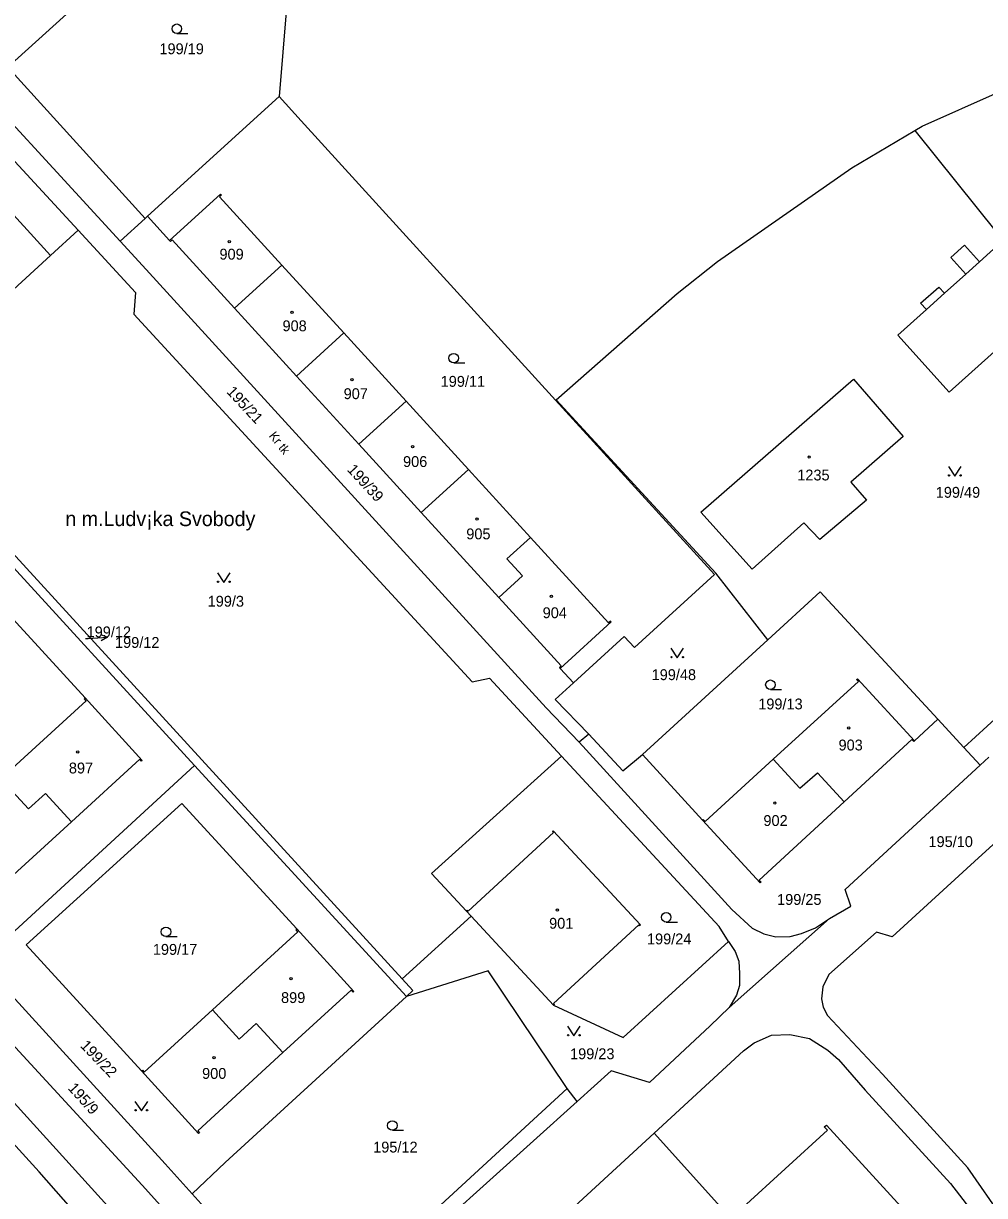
# Model space of a CAD drawing. Extents: x -735249 to -729401, y -1124843 to -1121828.
# Drawn here: x -733187.6 to -733037.1, y -1123958.8 to -1123775.2 of the extents above; entities that cross this region are included whole.
import ezdxf

# ---------------------------------------------------------------- set-up
doc = ezdxf.new("R2010")
doc.units = 0
for name, color, linetype in [('Vrstva 1', 7, 'Continuous'), ('Vrstva 15', 7, 'Continuous'), ('Vrstva 16', 7, 'Continuous'), ('Vrstva 18', 7, 'Continuous'), ('Vrstva 19', 7, 'Continuous'), ('Vrstva 25', 7, 'Continuous'), ('Vrstva 4', 7, 'Continuous')]:
    doc.layers.add(name, color=color, linetype=linetype)

msp = doc.modelspace()

# ---------------------------------------------------------------- linework, layer by layer
at = {"layer": 'Vrstva 1'}
for points in [[(-733144.76, -1123752.48), (-733147.59, -1123786.65)], [(-733178.16, -1123771.22), (-733190.05, -1123782.03)], [(-733172.46, -1123809.29), (-733201.09, -1123778.17)], [(-733179.06, -1123807.6), (-733203.9, -1123780.69)], [(-733046.92, -1123791.3), (-733023.02, -1123780.65)], [(-733168.57, -1123805.75), (-733190.05, -1123782.03)], [(-733147.59, -1123786.65), (-733168.2, -1123805.41)], [(-733147.59, -1123786.65), (-733144.14, -1123790.44)], [(-733144.14, -1123790.44), (-733104.3, -1123834.22)], [(-733057.93, -1123797.79), (-733048.04, -1123791.96)], [(-733048.04, -1123791.96), (-733046.92, -1123791.3)], [(-733048.04, -1123791.96), (-733035.11, -1123808.11)], [(-733183.39, -1123811.57), (-733200.21, -1123793.04)], [(-733078.95, -1123812.49), (-733057.93, -1123797.79)], [(-733164.73, -1123809.22), (-733156.74, -1123801.93)], [(-733156.62, -1123802.06), (-733156.93, -1123802.34)], [(-733156.93, -1123802.34), (-733147.17, -1123813.04)], [(-733156.74, -1123801.93), (-733156.62, -1123802.06)], [(-733168.2, -1123805.41), (-733168.57, -1123805.75)], [(-733168.2, -1123805.41), (-733164.73, -1123809.22)], [(-733168.57, -1123805.75), (-733172.46, -1123809.29)], [(-733183.39, -1123811.57), (-733179.06, -1123807.6)], [(-733179.06, -1123807.6), (-733170.05, -1123817.34)], [(-733164.61, -1123809.35), (-733164.73, -1123809.22)], [(-733164.31, -1123809.08), (-733164.61, -1123809.35)], [(-733154.55, -1123819.78), (-733164.31, -1123809.08)], [(-733172.46, -1123809.29), (-733168.97, -1123813.09)], [(-733042.41, -1123811.85), (-733040.27, -1123809.92)], [(-733040.27, -1123809.92), (-733037.92, -1123812.52)], [(-733037.92, -1123812.52), (-733034.6, -1123809.52)], [(-733209.79, -1123835.76), (-733183.39, -1123811.57)], [(-733085.28, -1123817.5), (-733078.95, -1123812.49)], [(-733040.06, -1123814.45), (-733042.41, -1123811.85)], [(-733105.77, -1123882.37), (-733168.97, -1123813.09)], [(-733154.55, -1123819.78), (-733147.17, -1123813.04)], [(-733147.17, -1123813.04), (-733137.46, -1123823.68)], [(-733043.41, -1123817.46), (-733040.06, -1123814.45)], [(-733047.18, -1123819), (-733044.29, -1123816.49)], [(-733044.29, -1123816.49), (-733043.41, -1123817.46)], [(-733170.05, -1123817.34), (-733170.32, -1123820.71)], [(-733104.21, -1123834.14), (-733085.28, -1123817.5)], [(-733144.85, -1123830.42), (-733154.55, -1123819.78)], [(-733050.7, -1123824.03), (-733046.25, -1123820.02)], [(-733046.25, -1123820.02), (-733047.18, -1123819)], [(-733170.32, -1123820.71), (-733117.36, -1123878.34)], [(-733144.85, -1123830.42), (-733137.46, -1123823.68)], [(-733137.46, -1123823.68), (-733127.69, -1123834.38)], [(-733042.66, -1123832.95), (-733050.7, -1123824.03)], [(-733034.6, -1123825.69), (-733042.66, -1123832.95)], [(-733135.08, -1123841.12), (-733144.85, -1123830.42)], [(-733081.56, -1123851.73), (-733057.66, -1123830.93)], [(-733057.66, -1123830.93), (-733049.86, -1123839.89)], [(-733127.69, -1123834.38), (-733135.08, -1123841.12)], [(-733117.93, -1123845.08), (-733127.69, -1123834.38)], [(-733104.3, -1123834.22), (-733104.21, -1123834.14)], [(-733079.44, -1123861.53), (-733104.3, -1123834.22)], [(-733079.19, -1123861.3), (-733104.21, -1123834.14)], [(-733128.3, -1123924.85), (-733207.89, -1123837.84)], [(-733049.86, -1123839.89), (-733058.07, -1123847.04)], [(-733135.08, -1123841.12), (-733125.32, -1123851.82)], [(-733125.32, -1123851.82), (-733117.93, -1123845.08)], [(-733108.23, -1123855.72), (-733117.93, -1123845.08)], [(-733058.07, -1123847.04), (-733055.61, -1123849.87)], [(-733055.61, -1123849.87), (-733062.93, -1123856.05)], [(-733125.32, -1123851.82), (-733113.19, -1123865.12)], [(-733073.54, -1123860.66), (-733081.56, -1123851.73)], [(-733065.42, -1123853.43), (-733073.54, -1123860.66)], [(-733062.93, -1123856.05), (-733065.42, -1123853.43)], [(-733160.83, -1123891.42), (-733193.72, -1123855.51)], [(-733111.91, -1123859.07), (-733108.23, -1123855.72)], [(-733096.03, -1123869.09), (-733108.23, -1123855.72)], [(-733109.48, -1123861.73), (-733111.91, -1123859.07)], [(-733195.56, -1123861.65), (-733177.93, -1123880.85)], [(-733113.19, -1123865.12), (-733109.48, -1123861.73)], [(-733079.44, -1123861.53), (-733091.96, -1123872.95)], [(-733071.09, -1123871.72), (-733079.19, -1123861.3)], [(-733071.09, -1123871.72), (-733062.89, -1123864.2)], [(-733062.89, -1123864.2), (-733044.46, -1123884.19)], [(-733113.19, -1123865.12), (-733103.42, -1123875.83)], [(-733103.59, -1123876.23), (-733095.59, -1123868.93)], [(-733095.71, -1123868.8), (-733096.03, -1123869.09)], [(-733095.59, -1123868.93), (-733095.71, -1123868.8)], [(-733093.54, -1123871.22), (-733101.52, -1123878.5)], [(-733091.96, -1123872.95), (-733093.54, -1123871.22)], [(-733090.71, -1123889.71), (-733071.09, -1123871.72)], [(-733103.42, -1123875.83), (-733103.71, -1123876.1)], [(-733103.71, -1123876.1), (-733103.59, -1123876.23)], [(-733103.59, -1123876.23), (-733101.52, -1123878.5)], [(-733117.36, -1123878.34), (-733114.67, -1123877.73)], [(-733114.67, -1123877.73), (-733103.39, -1123889.99)], [(-733101.52, -1123878.5), (-733104.35, -1123881.08)], [(-733070.21, -1123890.42), (-733056.9, -1123878.27)], [(-733057.18, -1123877.96), (-733057.05, -1123877.84)], [(-733056.9, -1123878.27), (-733057.18, -1123877.96)], [(-733057.05, -1123877.84), (-733048.09, -1123887.54)], [(-733191.13, -1123893.51), (-733177.78, -1123881.28)], [(-733178.06, -1123880.97), (-733177.93, -1123880.85)], [(-733177.78, -1123881.28), (-733178.06, -1123880.97)], [(-733177.93, -1123880.85), (-733169.01, -1123890.64)], [(-733100.62, -1123887.79), (-733105.77, -1123882.37)], [(-733104.35, -1123881.08), (-733099.07, -1123886.54)], [(-733044.46, -1123884.19), (-733048.09, -1123887.54)], [(-733040.37, -1123888.63), (-733044.46, -1123884.19)], [(-733034.89, -1123883.58), (-733040.37, -1123888.63)], [(-733099.07, -1123886.54), (-733100.62, -1123887.79)], [(-733100.62, -1123887.79), (-733076.73, -1123913.96)], [(-733099.07, -1123886.54), (-733093.78, -1123892.27)], [(-733048.51, -1123887.33), (-733059.13, -1123897.13)], [(-733048.21, -1123887.66), (-733048.51, -1123887.33)], [(-733048.09, -1123887.54), (-733048.21, -1123887.66)], [(-733103.39, -1123889.99), (-733123.72, -1123908.34)], [(-733078.68, -1123916.62), (-733103.39, -1123889.99)], [(-733093.78, -1123892.27), (-733090.71, -1123889.71)], [(-733090.71, -1123889.71), (-733081.32, -1123900)], [(-733037.82, -1123891.39), (-733040.37, -1123888.63)], [(-733194.28, -1123922.2), (-733160.83, -1123891.42)], [(-733169.4, -1123890.44), (-733180.1, -1123900.23)], [(-733169.11, -1123890.75), (-733169.4, -1123890.44)], [(-733169.01, -1123890.64), (-733169.11, -1123890.75)], [(-733160.83, -1123891.42), (-733127.66, -1123927.62)], [(-733080.9, -1123900.19), (-733070.21, -1123890.42)], [(-733070.21, -1123890.42), (-733066.04, -1123894.99)], [(-733058.94, -1123910.86), (-733037.82, -1123891.39)], [(-733037.82, -1123891.39), (-733036.46, -1123890.13)], [(-733191.13, -1123893.51), (-733186.8, -1123898.23)], [(-733066.04, -1123894.99), (-733063.31, -1123892.6)], [(-733063.31, -1123892.6), (-733059.13, -1123897.13)], [(-733187.19, -1123919.53), (-733162.82, -1123897.36)], [(-733186.8, -1123898.23), (-733184.15, -1123895.8)], [(-733184.15, -1123895.8), (-733180.1, -1123900.23)], [(-733162.82, -1123897.36), (-733144.81, -1123917.01)], [(-733059.13, -1123897.13), (-733072.42, -1123909.39)], [(-733038.11, -1123905.89), (-733029.67, -1123898.29)], [(-733180.1, -1123900.23), (-733193.45, -1123912.42)], [(-733081.32, -1123900), (-733081.19, -1123899.88)], [(-733072.25, -1123909.83), (-733081.32, -1123900)], [(-733081.19, -1123899.88), (-733080.9, -1123900.19)], [(-733118.01, -1123914.25), (-733104.64, -1123901.92)], [(-733104.79, -1123901.76), (-733104.66, -1123901.64)], [(-733104.64, -1123901.92), (-733104.79, -1123901.76)], [(-733104.66, -1123901.64), (-733091.02, -1123916.4)], [(-733051.62, -1123918.27), (-733038.11, -1123905.89)], [(-733123.72, -1123908.34), (-733118.27, -1123914.22)], [(-733072.42, -1123909.39), (-733072.12, -1123909.71)], [(-733072.12, -1123909.71), (-733072.25, -1123909.83)], [(-733058.05, -1123913.44), (-733058.94, -1123910.86)], [(-733061.43, -1123915.37), (-733058.05, -1123913.44)], [(-733208.75, -1123914.04), (-733169.04, -1123957.16)], [(-733128.3, -1123924.85), (-733117.52, -1123915.03)], [(-733118.27, -1123914.22), (-733118.15, -1123914.1)], [(-733118.27, -1123914.22), (-733117.52, -1123915.03)], [(-733118.15, -1123914.1), (-733118.01, -1123914.25)], [(-733104.61, -1123928.96), (-733117.52, -1123915.03)], [(-733077.12, -1123929.32), (-733061.43, -1123915.37)], [(-733076.73, -1123913.96), (-733073.51, -1123916.88)], [(-733063.61, -1123916.85), (-733061.43, -1123915.37)], [(-733158, -1123929.7), (-733144.65, -1123917.48)], [(-733144.93, -1123917.17), (-733144.81, -1123917.01)], [(-733144.65, -1123917.48), (-733144.93, -1123917.17)], [(-733144.81, -1123917.01), (-733135.87, -1123926.8)], [(-733091.27, -1123916.39), (-733104.61, -1123928.72)], [(-733091.15, -1123916.52), (-733091.27, -1123916.39)], [(-733091.02, -1123916.4), (-733091.15, -1123916.52)], [(-733077.22, -1123919), (-733078.68, -1123916.62)], [(-733073.51, -1123916.88), (-733071.71, -1123917.81)], [(-733065.78, -1123917.74), (-733063.61, -1123916.85)], [(-733054.06, -1123917.52), (-733061.5, -1123924.16)], [(-733051.62, -1123918.27), (-733054.06, -1123917.52)], [(-733093.71, -1123934.01), (-733077.22, -1123919)], [(-733077.22, -1123919), (-733076.18, -1123920.54)], [(-733071.71, -1123917.81), (-733069.83, -1123918.25)], [(-733069.83, -1123918.25), (-733067.58, -1123918.19)], [(-733067.58, -1123918.19), (-733065.78, -1123917.74)], [(-733187.19, -1123919.53), (-733169.11, -1123939.26)], [(-733076.18, -1123920.54), (-733075.61, -1123922.06)], [(-733165.4, -1123953.83), (-733194.28, -1123922.2)], [(-733075.61, -1123922.06), (-733075.51, -1123924.03)], [(-733207.24, -1123924.29), (-733171.44, -1123963.75)], [(-733126.63, -1123926.68), (-733128.3, -1123924.85)], [(-733114.83, -1123923.6), (-733127.66, -1123927.62)], [(-733102.48, -1123942.04), (-733114.83, -1123923.6)], [(-733075.51, -1123924.03), (-733075.48, -1123925.91)], [(-733061.5, -1123924.16), (-733062.45, -1123926.1)], [(-733136.29, -1123926.61), (-733146.98, -1123936.4)], [(-733136, -1123926.92), (-733136.29, -1123926.61)], [(-733127.66, -1123927.62), (-733126.63, -1123926.68)], [(-733075.48, -1123925.91), (-733075.98, -1123927.41)], [(-733062.45, -1123926.1), (-733062.69, -1123927.99)], [(-733127.66, -1123927.62), (-733156.03, -1123953.6)], [(-733135.87, -1123926.8), (-733136, -1123926.92)], [(-733075.98, -1123927.41), (-733077.12, -1123929.32)], [(-733062.69, -1123927.99), (-733062.38, -1123929.29)], [(-733168.7, -1123939.48), (-733158, -1123929.7)], [(-733158, -1123929.7), (-733153.82, -1123934.27)], [(-733104.61, -1123928.72), (-733104.49, -1123928.85)], [(-733104.49, -1123928.85), (-733104.61, -1123928.96)], [(-733104.61, -1123928.96), (-733093.71, -1123934.01)], [(-733077.12, -1123929.32), (-733080.12, -1123932.21)], [(-733062.38, -1123929.29), (-733061.72, -1123930.61)], [(-733153.82, -1123934.27), (-733151.16, -1123931.84)], [(-733151.16, -1123931.84), (-733146.98, -1123936.4)], [(-733080.12, -1123932.21), (-733089.6, -1123941.07)], [(-733061.72, -1123930.61), (-733053.11, -1123939.78)], [(-733073.19, -1123934.84), (-733070.5, -1123933.67)], [(-733070.5, -1123933.67), (-733067.65, -1123933.58)], [(-733067.65, -1123933.58), (-733064.56, -1123934.2)], [(-733074.87, -1123936.12), (-733073.19, -1123934.84)], [(-733064.56, -1123934.2), (-733061.69, -1123936.03)], [(-733146.98, -1123936.4), (-733160.33, -1123948.63)], [(-733088.87, -1123949.01), (-733074.87, -1123936.12)], [(-733061.69, -1123936.03), (-733059.98, -1123937.5)], [(-733059.98, -1123937.5), (-733055.83, -1123942.26)], [(-733169.11, -1123939.26), (-733168.99, -1123939.17)], [(-733160.18, -1123949.06), (-733169.11, -1123939.26)], [(-733168.99, -1123939.17), (-733168.7, -1123939.48)], [(-733095.6, -1123939.25), (-733100.92, -1123944.04)], [(-733089.6, -1123941.07), (-733095.6, -1123939.25)], [(-733053.11, -1123939.78), (-733039.77, -1123954.42)], [(-733102.48, -1123942.04), (-733137.43, -1123974.22)], [(-733100.92, -1123944.04), (-733102.48, -1123942.04)], [(-733055.83, -1123942.26), (-733042.49, -1123956.9)], [(-733185.13, -1123955.09), (-733194.66, -1123944.7)], [(-733121.44, -1123962.52), (-733100.92, -1123944.04)], [(-733160.33, -1123948.63), (-733160.05, -1123948.94)], [(-733074.99, -1123960.66), (-733061.72, -1123948.56)], [(-733062.23, -1123948), (-733061.86, -1123947.76)], [(-733061.72, -1123948.56), (-733062.23, -1123948)], [(-733061.86, -1123947.76), (-733048.52, -1123962.4)], [(-733160.05, -1123948.94), (-733160.18, -1123949.06)], [(-733127.52, -1123984.6), (-733088.87, -1123949.01)], [(-733088.87, -1123949.01), (-733077.07, -1123962.11)], [(-733161.17, -1123958.53), (-733165.4, -1123953.83)], [(-733156.03, -1123953.6), (-733161.17, -1123958.53)], [(-733177.51, -1123963.72), (-733185.13, -1123955.09)], [(-733034.17, -1123962.48), (-733039.77, -1123954.42)], [(-733169.04, -1123957.16), (-733147.71, -1123980.81)], [(-733042.49, -1123956.9), (-733039.12, -1123961.23)], [(-733149.46, -1123971.59), (-733161.17, -1123958.53)]]:
    msp.add_lwpolyline(points, dxfattribs=at)
at = {"layer": 'Vrstva 16'}
msp.add_lwpolyline([(-733177.92, -1123871.55), (-733177.46, -1123871.52)], dxfattribs=at)
at = {"layer": 'Vrstva 25'}
for points in [[(-733163.6, -1123776.78), (-733161.85, -1123776.78)], [(-733120.25, -1123828.37), (-733118.5, -1123828.37)], [(-733042.79, -1123844.59), (-733041.79, -1123846.09), (-733040.79, -1123844.59)], [(-733157.24, -1123861.24), (-733156.24, -1123862.74), (-733155.24, -1123861.24)], [(-733177.46, -1123871.52), (-733174.467, -1123871.316)], [(-733175.499, -1123870.886), (-733174.467, -1123871.316), (-733175.431, -1123871.882)], [(-733086.25, -1123873.06), (-733085.25, -1123874.56), (-733084.25, -1123873.06)], [(-733070.66, -1123879.53), (-733068.91, -1123879.53)], [(-733086.98, -1123915.95), (-733085.23, -1123915.95)], [(-733165.3, -1123918.23), (-733163.55, -1123918.23)], [(-733102.43, -1123932.28), (-733101.43, -1123933.78), (-733100.43, -1123932.28)], [(-733170.15, -1123944.03), (-733169.15, -1123945.53), (-733168.15, -1123944.03)], [(-733129.85, -1123948.56), (-733128.1, -1123948.56)]]:
    msp.add_lwpolyline(points, dxfattribs=at)
for centre, radius in [((-733163.6, -1123776.03), 0.75), ((-733155.38, -1123809.39), 0.175), ((-733145.56, -1123820.44), 0.175), ((-733120.25, -1123827.62), 0.75), ((-733136.18, -1123830.98), 0.175), ((-733126.68, -1123841.5), 0.175), ((-733064.6, -1123843.12), 0.175), ((-733042.69, -1123845.99), 0.1), ((-733040.89, -1123845.99), 0.1), ((-733116.59, -1123852.82), 0.175), ((-733157.14, -1123862.64), 0.1), ((-733155.34, -1123862.64), 0.1), ((-733104.95, -1123864.94), 0.175), ((-733086.15, -1123874.46), 0.1), ((-733084.35, -1123874.46), 0.1), ((-733070.66, -1123878.78), 0.75), ((-733058.4, -1123885.54), 0.175), ((-733179.11, -1123889.31), 0.175), ((-733069.97, -1123897.31), 0.175), ((-733104.02, -1123914.06), 0.175), ((-733086.98, -1123915.2), 0.75), ((-733165.3, -1123917.48), 0.75), ((-733145.71, -1123924.81), 0.175), ((-733102.33, -1123933.68), 0.1), ((-733100.53, -1123933.68), 0.1), ((-733157.76, -1123937.18), 0.175), ((-733170.05, -1123945.43), 0.1), ((-733168.25, -1123945.43), 0.1), ((-733129.85, -1123947.81), 0.75)]:
    msp.add_circle(centre, radius, dxfattribs=at)
at = {"layer": 'Vrstva 4'}
for points in [[(-733040.06, -1123814.45), (-733037.92, -1123812.52)], [(-733046.25, -1123820.02), (-733043.41, -1123817.46)]]:
    msp.add_lwpolyline(points, dxfattribs=at)

# ---------------------------------------------------------------- texts
at = {"layer": 'Vrstva 15'}
msp.add_text('Kr\xa0tk\xa0', height=1.4, rotation=308.40245, dxfattribs=at).set_placement((-733149.26, -1123839.812))
msp.add_text('n\xa0m.Ludv¡ka Svobody', height=2.29999, dxfattribs=at).set_placement((-733181.05, -1123853.93))
at = {"layer": 'Vrstva 16'}
msp.add_text('199/12', height=1.7, dxfattribs=at).set_placement((-733173.27, -1123873.01))
at = {"layer": 'Vrstva 18'}
for s, p in [('199/19', (-733166.32, -1123780.02)), ('199/11', (-733122.29, -1123832.11)), ('199/49', (-733044.78, -1123849.49)), ('199/3', (-733158.77, -1123866.55)), ('199/12', (-733177.72, -1123871.35)), ('199/48', (-733089.26, -1123878.05)), ('199/13', (-733072.57, -1123882.64)), ('195/10', (-733045.92, -1123904.2)), ('199/25', (-733069.62, -1123913.26)), ('199/17', (-733167.35, -1123921.08)), ('199/24', (-733089.99, -1123919.44)), ('199/23', (-733102.03, -1123937.43)), ('195/12', (-733132.86, -1123952.05))]:
    msp.add_text(s, height=1.7, dxfattribs=at).set_placement(p)
for s, rotation, p in [('195/21', 312.90249, (-733155.918, -1123832.96)), ('199/39', 312.60249, (-733137.028, -1123845.171)), ('199/22', 313.80249, (-733178.828, -1123935.415)), ('195/9', 312.00248, (-733180.748, -1123942.034))]:
    msp.add_text(s, height=1.7, rotation=rotation, dxfattribs=at).set_placement(p)
at = {"layer": 'Vrstva 19'}
for s, p in [('909', (-733156.92, -1123812.19)), ('908', (-733147.05, -1123823.41)), ('907', (-733137.48, -1123834.04)), ('906', (-733128.18, -1123844.67)), ('1235', (-733066.46, -1123846.78)), ('905', (-733118.28, -1123856)), ('904', (-733106.32, -1123868.35)), ('903', (-733060, -1123889.07)), ('897', (-733180.5, -1123892.67)), ('902', (-733071.76, -1123900.9)), ('901', (-733105.31, -1123916.99)), ('899', (-733147.28, -1123928.63)), ('900', (-733159.64, -1123940.51))]:
    msp.add_text(s, height=1.7, dxfattribs=at).set_placement(p)

doc.saveas('drawing.dxf')
